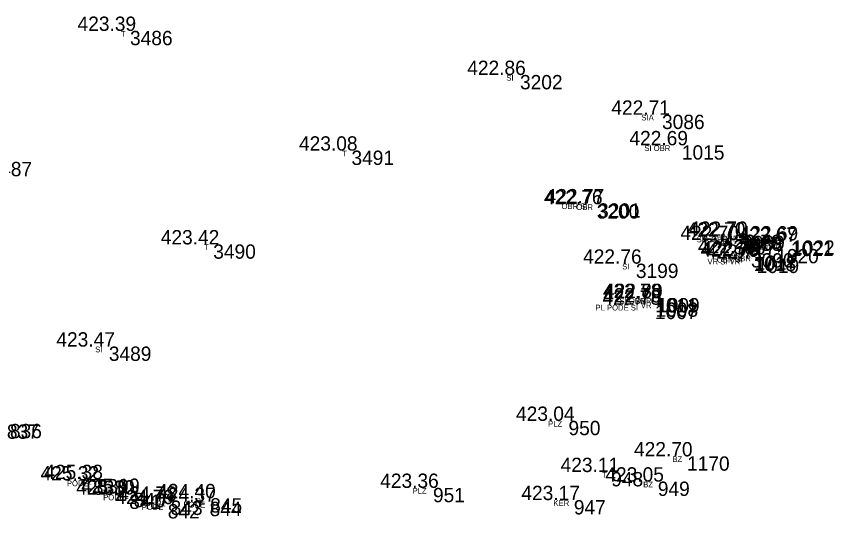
# Model space of a CAD drawing. Extents: x -639390 to -639075, y -1138747 to -1138358.
# Drawn here: x -639158.84 to -639116.02, y -1138646.87 to -1138620.57 of the extents above; entities that cross this region are included whole.
import ezdxf

# ---------------------------------------------------------------- set-up
doc = ezdxf.new("R2010")
doc.units = 0
for name, color, linetype in [('Vrstva 11', 7, 'Continuous'), ('Vrstva 12', 7, 'Continuous'), ('Vrstva 13', 7, 'Continuous'), ('Vrstva 57', 7, 'Continuous')]:
    doc.layers.add(name, color=color, linetype=linetype)

msp = doc.modelspace()

# ---------------------------------------------------------------- linework, layer by layer
at = {"layer": 'Vrstva 11'}
for p, q in [((-639153.16, -1138621.33), (-639153.16, -1138621.33)), ((-639132.73, -1138623.64), (-639132.73, -1138623.64)), ((-639125.29, -1138625.72), (-639125.29, -1138625.72)), ((-639124.25, -1138627.32), (-639124.25, -1138627.32)), ((-639141.56, -1138627.6), (-639141.56, -1138627.6)), ((-639128.64, -1138630.36), (-639128.64, -1138630.36)), ((-639128.71, -1138630.41), (-639128.71, -1138630.41)), ((-639121.09, -1138632.06), (-639121.09, -1138632.06)), ((-639148.8, -1138632.51), (-639148.8, -1138632.51)), ((-639121.55, -1138632.28), (-639121.55, -1138632.28)), ((-639121.21, -1138632.1), (-639121.21, -1138632.1)), ((-639118.54, -1138632.37), (-639118.54, -1138632.37)), ((-639118.48, -1138632.3), (-639118.48, -1138632.3)), ((-639119.31, -1138632.75), (-639119.31, -1138632.75)), ((-639120.63, -1138632.97), (-639120.63, -1138632.97)), ((-639120.5, -1138633.16), (-639120.5, -1138633.16)), ((-639120.44, -1138633.09), (-639120.44, -1138633.09)), ((-639120.34, -1138633.26), (-639120.34, -1138633.26)), ((-639126.66, -1138633.52), (-639126.66, -1138633.52)), ((-639125.64, -1138635.32), (-639125.64, -1138635.32)), ((-639125.55, -1138635.32), (-639125.55, -1138635.32)), ((-639125.66, -1138635.67), (-639125.66, -1138635.67)), ((-639125.63, -1138635.55), (-639125.63, -1138635.55)), ((-639154.27, -1138637.86), (-639154.27, -1138637.86)), ((-639130.19, -1138641.75), (-639130.19, -1138641.75)), ((-639123.98, -1138643.61), (-639123.98, -1138643.61)), ((-639127.95, -1138644.43), (-639127.95, -1138644.43)), ((-639155.1, -1138644.87), (-639155.1, -1138644.87)), ((-639154.9, -1138644.8), (-639154.9, -1138644.8)), ((-639125.51, -1138644.93), (-639125.51, -1138644.93)), ((-639137.29, -1138645.26), (-639137.29, -1138645.26)), ((-639153.2, -1138645.61), (-639153.2, -1138645.61)), ((-639152.97, -1138645.52), (-639152.97, -1138645.52)), ((-639151.18, -1138646.11), (-639151.18, -1138646.11)), ((-639151.03, -1138645.93), (-639151.03, -1138645.93)), ((-639148.99, -1138645.99), (-639148.99, -1138645.99)), ((-639148.96, -1138645.8), (-639148.96, -1138645.8)), ((-639129.91, -1138645.9), (-639129.91, -1138645.9))]:
    msp.add_line(p, q, dxfattribs=at)

# ---------------------------------------------------------------- texts
at = {"layer": 'Vrstva 12'}
for s, p in [('423.39 ', (-639155.629, -1138621.33)), ('422.86 ', (-639135.216, -1138623.64)), ('422.71 ', (-639127.665, -1138625.72)), ('423.08 ', (-639144.029, -1138627.6)), ('422.69 ', (-639126.719, -1138627.32)), ('422.76 ', (-639131.196, -1138630.41)), ('422.77 ', (-639131.109, -1138630.36)), ('422.70 ', (-639124.049, -1138632.28)), ('422.70 ', (-639123.709, -1138632.1)), ('422.70 ', (-639123.589, -1138632.06)), ('422.67 ', (-639121.009, -1138632.37)), ('422.69 ', (-639120.949, -1138632.3)), ('423.42 ', (-639151.269, -1138632.51)), ('422.70 ', (-639121.809, -1138632.75)), ('422.70 ', (-639123.129, -1138632.97)), ('422.70 ', (-639122.999, -1138633.16)), ('422.70 ', (-639122.939, -1138633.09)), ('422.71 ', (-639122.715, -1138633.26)), ('422.76 ', (-639129.146, -1138633.52)), ('422.78 ', (-639128.109, -1138635.32)), ('422.80 ', (-639128.049, -1138635.32)), ('422.78 ', (-639128.129, -1138635.67)), ('422.78 ', (-639128.099, -1138635.55)), ('423.47 ', (-639156.739, -1138637.86)), ('423.04 ', (-639132.659, -1138641.75)), ('422.70 ', (-639126.479, -1138643.61)), ('425.38 ', (-639157.369, -1138644.8)), ('423.11 ', (-639130.325, -1138644.43)), ('425.32 ', (-639157.569, -1138644.87)), ('423.36 ', (-639139.776, -1138645.26)), ('423.05 ', (-639127.98, -1138644.93)), ('425.10 ', (-639155.699, -1138645.61)), ('425.19 ', (-639155.439, -1138645.52)), ('424.79 ', (-639153.649, -1138646.11)), ('424.78 ', (-639153.499, -1138645.93)), ('424.40 ', (-639151.459, -1138645.8)), ('424.37 ', (-639151.459, -1138645.99)), ('423.17 ', (-639132.379, -1138645.9))]:
    msp.add_text(s, height=0.75, dxfattribs=at).set_placement(p)
at = {"layer": 'Vrstva 13'}
for s, p in [(' 3486', (-639153.16, -1138622.08)), (' 3202', (-639132.73, -1138624.39)), (' 3086', (-639125.29, -1138626.47)), (' 1015', (-639124.25, -1138628.07)), (' 3491', (-639141.56, -1138628.35)), (' 3487', (-639160.52, -1138628.94)), (' 3201', (-639128.64, -1138631.11)), (' 3200', (-639128.71, -1138631.16)), (' 3088', (-639121.21, -1138632.85)), (' 3089', (-639121.09, -1138632.81)), (' 3490', (-639148.8, -1138633.26)), (' 3087', (-639121.55, -1138633.03)), (' 1021', (-639118.54, -1138633.12)), (' 1022', (-639118.48, -1138633.05)), (' 1020', (-639119.31, -1138633.5)), (' 3090', (-639120.63, -1138633.72)), (' 1018', (-639120.5, -1138633.91)), (' 1017', (-639120.44, -1138633.84)), (' 1019', (-639120.34, -1138634.01)), (' 3199', (-639126.66, -1138634.27)), (' 1011', (-639125.64, -1138636.07)), (' 1009', (-639125.55, -1138636.07)), (' 1007', (-639125.66, -1138636.42)), (' 1008', (-639125.63, -1138636.3)), (' 3489', (-639154.27, -1138638.61)), (' 837', (-639159.61, -1138642.69)), (' 836', (-639159.45, -1138642.66)), (' 950', (-639130.19, -1138642.5)), (' 1170', (-639123.98, -1138644.36)), (' 948', (-639127.95, -1138645.18)), (' 838', (-639155.1, -1138645.62)), (' 839', (-639154.9, -1138645.55)), (' 949', (-639125.51, -1138645.68)), (' 951', (-639137.29, -1138646.01)), (' 841', (-639153.2, -1138646.36)), (' 840', (-639152.97, -1138646.27)), (' 845', (-639148.96, -1138646.55)), (' 842', (-639151.18, -1138646.86)), (' 843', (-639151.03, -1138646.68)), (' 844', (-639148.99, -1138646.74)), (' 947', (-639129.91, -1138646.65))]:
    msp.add_text(s, height=0.75, dxfattribs=at).set_placement(p)
at = {"layer": 'Vrstva 57'}
for s, p in [('T', (-639153.36, -1138621.63)), ('SI', (-639133.168, -1138623.94)), ('SIA', (-639126.09, -1138626.02)), ('SI OBR', (-639125.939, -1138627.62)), ('T', (-639141.76, -1138627.9)), ('OBR SI', (-639130.278, -1138630.66)), ('OBR', (-639129.499, -1138630.71)), ('OBR', (-639121.879, -1138632.36)), ('T', (-639149, -1138632.81)), ('SIA OBR', (-639123.199, -1138632.4)), ('SIA', (-639122.35, -1138632.58)), ('PLZ OBR', (-639120.469, -1138632.6)), ('PLZ SI', (-639120.178, -1138632.67)), ('VR PLZ', (-639120.999, -1138633.05)), ('VR SI VR', (-639122.629, -1138633.56)), ('OBR SI', (-639122.138, -1138633.46)), ('SIA', (-639121.43, -1138633.27)), ('OBR', (-639121.229, -1138633.39)), ('SI', (-639127.098, -1138633.82)), ('SI OBR', (-639127.239, -1138635.62)), ('OBR', (-639126.429, -1138635.62)), ('PL PODE SI', (-639128.498, -1138635.97)), ('VR', (-639126.119, -1138635.85)), ('SI', (-639154.708, -1138638.16)), ('PLZ', (-639130.979, -1138642.05)), ('BZ', (-639124.469, -1138643.91)), ('T', (-639128.15, -1138644.73)), ('PODE', (-639156.188, -1138645.17)), ('PL', (-639155.375, -1138645.1)), ('BZ', (-639125.999, -1138645.23)), ('PLZ', (-639138.079, -1138645.56)), ('PODE', (-639154.287, -1138645.91)), ('PL', (-639153.445, -1138645.82)), ('PODE', (-639152.267, -1138646.41)), ('PL', (-639151.505, -1138646.23)), ('PODE', (-639150.078, -1138646.29)), ('PL', (-639149.435, -1138646.1)), ('KER', (-639130.699, -1138646.2))]:
    msp.add_text(s, height=0.3, dxfattribs=at).set_placement(p)

doc.saveas('drawing.dxf')
